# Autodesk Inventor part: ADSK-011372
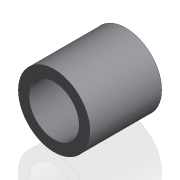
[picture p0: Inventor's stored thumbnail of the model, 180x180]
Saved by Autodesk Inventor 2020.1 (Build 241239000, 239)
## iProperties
Created: 2000-02
Part Number: ADSK-011372
Material: Pearson HRS
Document SubType Name: Modeling
Designer: glanglot
Density: 7.83 g/cm^3
Appearance: Métal - Acier
Mass: 6.73724 g
Surface Area: 9.90304 cm^2
Volume: 0.86044 cm^3
Control State: 0
Checked Out: False
Master: False
Shininess: 0.0
Length Units: 11269
Angle Units: 11279
Time Units: 11290
Mass Units: 11283
Length Display Precision: 3
Angle Display Precision: 2
Compacted: True
Dimensions: 12,5x12,5x12,5 mm
Mass: 0,007 kg
Density: 0.0
Volumn: 0.0
Area: 0.0
PropertySet Name: Model Information
Author: glanglot
Revision Number: -
Title: ADSK-011372
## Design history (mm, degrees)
node "Solide1"
  node "Extrusion1" dims "d1" = 12.5, "d2" = 0
  node "Hole1" dims "d3" = 6.647, "d4" = 8.73125, "d5" = 9.525, "d6" = 60 deg, "d7" = 22.2, "d8" = 118 deg, "d9" = 16
sketch "Sketch1"
  geometry: C1 r 6.25 at (0, 0); 2 further points
  constraints: 2 coincident, 1 centre point
  dimensions: "d0" = 12.5 diameter of C1
node "Corps solides"
node "Corps surfaciques"
